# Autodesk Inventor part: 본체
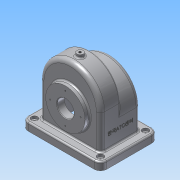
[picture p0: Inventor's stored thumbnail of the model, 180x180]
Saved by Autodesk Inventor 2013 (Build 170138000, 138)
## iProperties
Created: 2017-11
Part Number: 본체
Material: 알루미늄 6061
Document SubType Name: Modeling
Designer: Administrator
Density: 2.71 g/cm^3
Mass: 1079.49 g
Surface Area: 1182.07 cm^2
Volume: 398.335 cm^3
Author: Administrator
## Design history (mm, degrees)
sketch "스케치4"
  geometry: L1 (-58, 15)-(58, 15); L2 (58, 15)-(58, -65); L3 (58, -65)-(-58, -65); L4 (-58, -65)-(-58, 15); A1 r 58 centre (0, 15) between (58, 15) and (-58, 15); 2 further points
  constraints: 8 end point, 2 midpoint, 2 parallel, 2 point on circle, 2 vertical alignment, 1 centre point, 1 horizontal, 1 perpendicular
  dimensions: "d4" = 116 distance of L2.end L3.end; "d5" = 80 distance of L1.end L2.end; "d7" = 65 distance of point (0, -65) point (0, 0)
extrude "돌출1" new body sketch "스케치4" distance "d8" = 38; taper "d9" = 0 deg
sketch "스케치6"
  geometry: L1 (-58, -65)-(-58, 15) reference; L2 (58, -65)-(-58, -65) reference; L3 (-58, -8)-(58, -8); L4 (58, -8)-(58, -65); L5 (58, -65)-(-58, -65); L6 (-58, -65)-(-58, -8); A1 r 58 centre (0, -8) between (58, -8) and (-58, -8); 1 further point
  constraints: 8 end point, 2 parallel, 2 point on circle, 1 centre point, 1 horizontal, 1 midpoint, 1 perpendicular, 1 point on line
  dimensions: "d10" = 57 distance between parallel lines of L2 L3
extrude "돌출2" join sketch "스케치6" distance "d12" = 38; taper "d13" = 0 deg
feature "쉘1" dims "d14" = 5
sketch "스케치7"
  geometry: C1 r 31 at (0, 0); 1 further point
  constraints: 1 centre point, 1 coincident
  dimensions: "d15" = 62 diameter of C1
extrude "돌출3" join sketch "스케치7" distance "d16" = 10; taper "d17" = 0 deg
sketch "스케치8"
  geometry: C1 r 31 at (0, 0) reference; C2 r 16 at (0, 0)
  constraints: 1 centre point, 1 coincident
  dimensions: "d18" = 32 diameter of C2
extrude "돌출4" cut sketch "스케치8" stored distance "d19" = 10; taper "d20" = 0 deg
sketch "스케치9"
  geometry: C1 r 16 at (0, 0) reference; C2 r 37.5 at (0, 0)
  constraints: 1 centre point, 1 coincident
  dimensions: "d21" = 75 diameter of C2
extrude "돌출5" join sketch "스케치9" distance "d22" = 9; taper "d23" = 0 deg
sketch "스케치10"
  geometry: C1 r 16 at (0, 0) reference; 1 further point
  constraints: 1 vertical alignment
  dimensions: "d24" = 29 distance of C1.centre point (0, 29)
hole "구멍1" sketch "스케치10" at (0, 29) diameter "d25" = 2.459; stored, may be unused: countersink angle "d29" = 90 deg, drill point angle "d31" = 118 deg; dims "d26" = 6, "d27" = 4, "d28" = 2, "d30" = 8
sketch "스케치11"
  geometry: C1 r 16 at (0, 0) reference; 1 further point
  constraints: 1 vertical alignment
  dimensions: "d35" = 26 distance of point (0, 26) C1.centre
hole "구멍2" sketch "스케치11" at (0, 26) diameter "d36" = 2.459; stored, may be unused: countersink angle "d40" = 90 deg, drill point angle "d42" = 118 deg; dims "d37" = 6, "d38" = 4, "d39" = 2, "d41" = 8
sketch "스케치12"
  geometry: L1 (116, -76)-(116, 0) reference; L2 (0, 0)-(116, 0) reference; L3 (0, -76)-(0, 0) reference; L4 (116, -76)-(0, -76) reference; L5 (133, 17)-(-17, 17); L6 (-17, 17)-(-17, -93); L7 (-17, -93)-(133, -93); L8 (133, -93)-(133, 17); 1 further point
  constraints: 8 end point, 2 parallel, 1 horizontal, 1 perpendicular
  dimensions: "d48" = 150 distance of L6.end L7.end; "d49" = 55 distance from line of point (58, -38) L5; "d50" = 75 horizontal distance of point (58, -38) L7.end; "d51" = 110 distance of L7.end L5.start
extrude "돌출6" join sketch "스케치12" distance "d52" = 15; taper "d53" = 0 deg
fillet "모깎기1" dims "d54" = 12
sketch "스케치13"
  geometry: A1 r 12 centre (-5, 81) between (-5, 93) and (-17, 81) reference; 2 further points
  constraints: 1 coincident
hole "구멍3" sketch "스케치13" at (-5, 81) diameter "d55" = 5; stored, may be unused: countersink angle "d59" = 90 deg, drill point angle "d61" = 0 deg; dims "d56" = 6, "d57" = 12, "d58" = 5, "d60" = 8
node "작업 평면1"
sketch "스케치14"
  geometry: L1 (-5, 93)-(-121, 93) reference; C1 r 6 at (-63, 74); 1 further point
  constraints: 1 centre point, 1 vertical alignment
  dimensions: "d64" = 12 diameter of C1; "d65" = 19 distance from line of C1.centre L1
extrude "돌출7" join sketch "스케치14" stored distance "d66" = 15; taper "d67" = 0 deg
hole "구멍4" diameter "d70" = 4.459; stored, may be unused: countersink angle "d74" = 90 deg, drill point angle "d76" = 118 deg; dims "d68" = 10, "d69" = 10, "d71" = 6, "d72" = 12, "d73" = 5, "d75" = 8
fillet "모깎기7" dims "d85" = 8
fillet "모깎기8" dims "d86" = 3
fillet "모깎기9" dims "d87" = 3
fillet "모깎기10" dims "d88" = 3
chamfer "모따기2" distance "d89" = 1; stored, may be unused: second distance "d90" = 2, angle "d91" = 45 deg
fillet "모깎기11" dims "d92" = 3
sketch "스케치15"
  geometry: L1 (-35, 23)-(-35, -39) reference; L2 (46, -57)-(-40, -57) reference; 2 further points
  constraints: 1 other
  dimensions: "d93" = 38 distance from line of point (3, -17) L1; "d94" = 40 distance from line of point (3, -17) L2
feature "엠보싱1" sketch "스케치15" dims "d4" = 116, "d5" = 80, "d7" = 65, "d95" = 0.5, "d96" = 0
node "솔리드1"
pattern_circular "원형 패턴1" dims angle "d33" = 360 deg
pattern_circular "원형 패턴2" dims angle "d44" = 360 deg
mirror "대칭1"
mirror "대칭2"
other parameters: "d62" = -144
